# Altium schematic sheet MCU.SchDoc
size A4; Revision: C.2
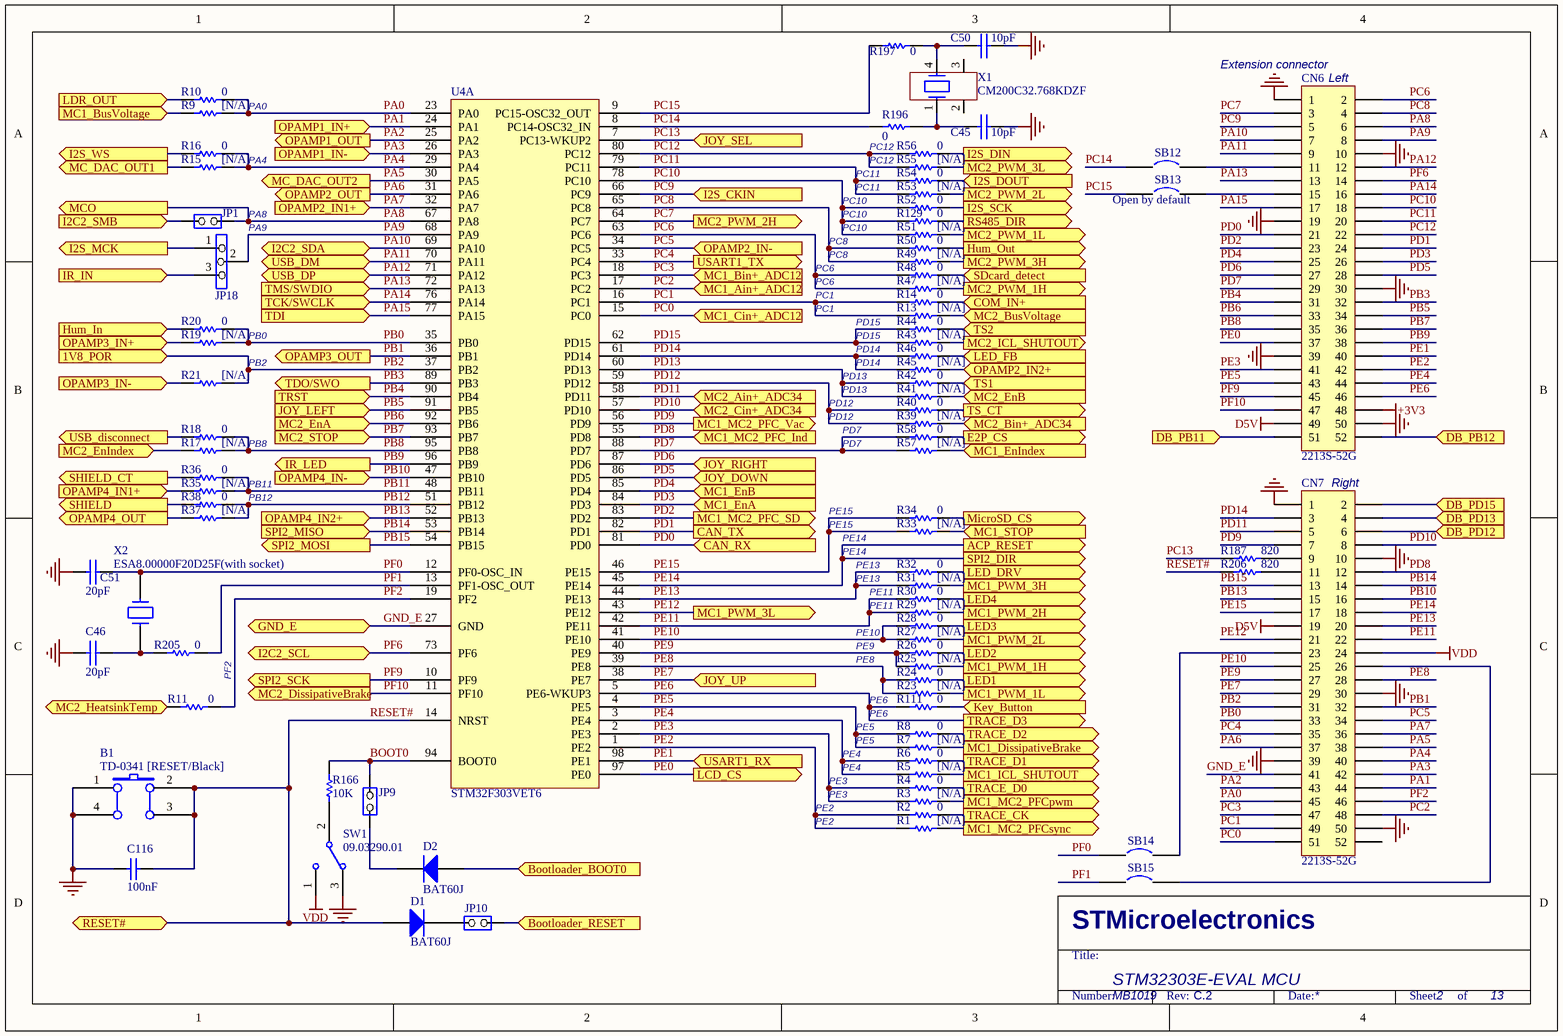
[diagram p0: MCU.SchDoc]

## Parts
B1  TD-0341 [RESET/Black]  [PB10]
C45  10pF  [0603C]
C46  20pF  [0603C]
C50  10pF  [0603C]
C51  20pF  [0603C]
C116  100nF  [0603C]
CN6  2213S-52G  [2*26P]
CN7  2213S-52G  [2*26P]
D1  BAT60J  [SOD-323]
D2  BAT60J  [SOD-323]
JP1  (no value)  [SIP2]
JP9  (no value)  [SIP2]
JP10  (no value)  [SIP2]
JP18  (no value)  [SIP3]
R1  [N/A]  [0603R]
R2  0  [0603R]
R3  [N/A]  [0603R]
R4  0  [0603R]
R5  [N/A]  [0603R]
R6  0  [0603R]
R7  [N/A]  [0603R]
R8  0  [0603R]
R9  [N/A]  [0603R]
R10  0  [0603R]
R11  0  [0603R]
R13  [N/A]  [0603R]
R14  0  [0603R]
R15  [N/A]  [0603R]
R16  0  [0603R]
R17  [N/A]  [0603R]
R18  0  [0603R]
R19  [N/A]  [0603R]
R20  0  [0603R]
R21  [N/A]  [0603R]
R23  [N/A]  [0603R]
R24  0  [0603R]
R25  [N/A]  [0603R]
R26  0  [0603R]
R27  [N/A]  [0603R]
R28  0  [0603R]
R29  [N/A]  [0603R]
R30  0  [0603R]
R31  [N/A]  [0603R]
R32  0  [0603R]
R33  [N/A]  [0603R]
R34  0  [0603R]
R35  [N/A]  [0603R]
R36  0  [0603R]
R37  [N/A]  [0603R]
R38  0  [0603R]
R39  [N/A]  [0603R]
R40  0  [0603R]
R41  [N/A]  [0603R]
R42  0  [0603R]
R43  [N/A]  [0603R]
R44  0  [0603R]
R45  [N/A]  [0603R]
R46  0  [0603R]
R47  [N/A]  [0603R]
R48  0  [0603R]
R49  [N/A]  [0603R]
R50  0  [0603R]
R51  [N/A]  [0603R]
R52  0  [0603R]
R53  [N/A]  [0603R]
R54  0  [0603R]
R55  [N/A]  [0603R]
R56  0  [0603R]
R57  [N/A]  [0603R]
R58  0  [0603R]
R111  0  [0603R]
R129  0  [0603R]
R166  10K  [0603R]
R187  820  [0603R]
R196  0  [0603R]
R197  0  [0603R]
R205  0  [0603R]
R206  820  [0603R]
SB12  (no value)  [JP2_SMD]
SB13  (no value)  [JP2_SMD]
SB14  (no value)  [JP2_SMD]
SB15  (no value)  [JP2_SMD]
SW1  09.03290.01  [SIP3]
U4  STM32F303VET6  [IC149-100-025-B5]  (part A of 2)
X1  CM200C32.768KDZF  [SM8]
X2  ESA8.00000F20D25F(with socket)  [XTAL_socket]

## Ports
1V8_POR (in), ACP_RESET (out), Bootloader_BOOT0 (in), Bootloader_RESET (in), CAN_RX (in), CAN_TX (out), COM_IN+ (in), DB_PB11 (in), DB_PB12 (in), DB_PD12 (in), DB_PD13 (in), DB_PD15 (in), E2P_CS (out), GND_E (bidir), Hum_In (in), Hum_Out (out), I2C2_SCL (bidir), I2C2_SDA (bidir), I2C2_SMB (in), I2S_CKIN (in), I2S_DIN (out), I2S_DOUT (in), I2S_MCK (out), I2S_SCK (out), I2S_WS (out), IR_IN (in), IR_LED (out), JOY_DOWN (in), JOY_LEFT (in), JOY_RIGHT (in), JOY_SEL (in), JOY_UP (in), Key_Button (in), LCD_CS (out), LDR_OUT (in), LED1 (out), LED2 (out), LED3 (out), LED4 (out), LED_DRV (out), LED_FB (in), MC1_Ain+_ADC12 (in), MC1_Bin+_ADC12 (in), MC1_BusVoltage (in), MC1_Cin+_ADC12 (in), MC1_DissipativeBrake (out), MC1_EnA (in), MC1_EnB (in), MC1_EnIndex (in), MC1_ICL_SHUTOUT (out), MC1_MC2_PFC_Ind (in), MC1_MC2_PFC_SD (out), MC1_MC2_PFC_Vac (out), MC1_MC2_PFCpwm (out), MC1_MC2_PFCsync (out), MC1_PWM_1H (out), MC1_PWM_1L (out), MC1_PWM_2H (out), MC1_PWM_2L (out), MC1_PWM_3H (out), MC1_PWM_3L (out), MC1_STOP (in), MC2_Ain+_ADC34 (in), MC2_Bin+_ADC34 (in), MC2_BusVoltage (in), MC2_Cin+_ADC34 (in), MC2_DissipativeBrake (out), MC2_EnA (in), MC2_EnB (in), MC2_EnIndex (in), MC2_HeatsinkTemp (in), MC2_ICL_SHUTOUT (out), MC2_PWM_1H (out), MC2_PWM_1L (out), MC2_PWM_2H (out), MC2_PWM_2L (out), MC2_PWM_3H (out), MC2_PWM_3L (out), MC2_STOP (in), MC_DAC_OUT1 (out), MC_DAC_OUT2 (out), MCO (out), MicroSD_CS (out), OPAMP1_IN+ (in), OPAMP1_IN- (in), OPAMP1_OUT (out), OPAMP2_IN1+ (in), OPAMP2_IN2+ (in), OPAMP2_IN- (in), OPAMP2_OUT (out), OPAMP3_IN+ (in), OPAMP3_IN- (in), OPAMP3_OUT (out), OPAMP4_IN1+ (in), OPAMP4_IN2+ (in), OPAMP4_IN- (in), OPAMP4_OUT (out), RESET# (bidir), RS485_DIR (out), SDcard_detect (in), SHIELD (out), SHIELD_CT (out), SPI2_DIR (out), SPI2_MISO (in), SPI2_MOSI (out), SPI2_SCK (out), TCK/SWCLK (in), TDI (in), TDO/SWO (out), TMS/SWDIO (in), TRACE_CK (out), TRACE_D0 (out), TRACE_D1 (out), TRACE_D2 (out), TRACE_D3 (out), TRST (in), TS1 (in), TS2 (in), TS_CT (out), USART1_RX (in), USART1_TX (out), USB_disconnect (out), USB_DM (bidir), USB_DP (bidir)

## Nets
+3V3: CN6.48
D5V: CN6.49 CN7.19
GND: B1.1(A0) B1.4(A1) C45.2 C46.2 C50.2 C51.2 C116.1 CN6.1 CN6.10 CN6.19 CN6.30 CN6.39 CN6.50 CN7.1 CN7.10 CN7.30 CN7.39 CN7.50 SW1.3
VDD: CN7.24 SW1.1
BOOT0: JP9.2(NO) R166.1 U4.94(BOOT0)
Bootloader_BOOT0: D2.1(A) ; port Bootloader_BOOT0
Bootloader_RESET: JP10.2(NO) ; port Bootloader_RESET
COM_IN+: R14.1 ; port COM_IN+
DB_PB11: CN6.51 ; port DB_PB11
DB_PB12: CN6.52 ; port DB_PB12
DB_PD12: CN7.6 ; port DB_PD12
DB_PD13: CN7.4 ; port DB_PD13
DB_PD15: CN7.2 ; port DB_PD15
E2P_CS: R58.1 ; port E2P_CS
GND_E: CN7.41 U4.27(GND) ; port GND_E
Hum_In: R20.2 ; port Hum_In
Hum_Out: R50.1 ; port Hum_Out
I2C2_SMB: JP1.2(NO) ; port I2C2_SMB
I2S_DIN: R56.1 ; port I2S_DIN
I2S_DOUT: R54.1 ; port I2S_DOUT
I2S_MCK: JP18.1 ; port I2S_MCK
I2S_SCK: R52.1 ; port I2S_SCK
I2S_WS: R16.2 ; port I2S_WS
IR_IN: JP18.3 ; port IR_IN
Key_Button: R111.1 ; port Key_Button
LDR_OUT: R10.2 ; port LDR_OUT
LED1: R24.1 ; port LED1
LED2: R26.1 ; port LED2
LED3: R28.1 ; port LED3
LED4: R30.1 ; port LED4
LED_DRV: R32.1 ; port LED_DRV
LED_FB: R46.1 ; port LED_FB
MC1_BusVoltage: R9.2 ; port MC1_BusVoltage
MC1_DissipativeBrake: R7.1 ; port MC1_DissipativeBrake
MC1_EnIndex: R57.1 ; port MC1_EnIndex
MC1_ICL_SHUTOUT: R5.1 ; port MC1_ICL_SHUTOUT
MC1_MC2_PFCpwm: R3.1 ; port MC1_MC2_PFCpwm
MC1_MC2_PFCsync: R1.1 ; port MC1_MC2_PFCsync
MC1_PWM_1H: R25.1 ; port MC1_PWM_1H
MC1_PWM_1L: R23.1 ; port MC1_PWM_1L
MC1_PWM_2H: R29.1 ; port MC1_PWM_2H
MC1_PWM_2L: R27.1 ; port MC1_PWM_2L
MC1_PWM_3H: R31.1 ; port MC1_PWM_3H
MC1_STOP: R33.1 ; port MC1_STOP
MC2_Bin+_ADC34: R39.1 ; port MC2_Bin+_ADC34
MC2_BusVoltage: R13.1 ; port MC2_BusVoltage
MC2_EnB: R41.1 ; port MC2_EnB
MC2_EnIndex: R17.2 ; port MC2_EnIndex
MC2_HeatsinkTemp: R11.2 ; port MC2_HeatsinkTemp
MC2_ICL_SHUTOUT: R43.1 ; port MC2_ICL_SHUTOUT
MC2_PWM_1H: R47.1 ; port MC2_PWM_1H
MC2_PWM_1L: R51.1 ; port MC2_PWM_1L
MC2_PWM_2L: R53.1 ; port MC2_PWM_2L
MC2_PWM_3H: R49.1 ; port MC2_PWM_3H
MC2_PWM_3L: R55.1 ; port MC2_PWM_3L
MC_DAC_OUT1: R15.2 ; port MC_DAC_OUT1
MicroSD_CS: R34.1 ; port MicroSD_CS
OPAMP2_IN2+: R45.1 ; port OPAMP2_IN2+
OPAMP3_IN+: R19.2 ; port OPAMP3_IN+
OPAMP3_IN-: R21.2 ; port OPAMP3_IN-
OPAMP4_IN1+: R35.2 ; port OPAMP4_IN1+
OPAMP4_OUT: R37.2 ; port OPAMP4_OUT
PA0: CN7.45 R9.1 R10.1 U4.23(PA0)
PA1: CN7.44 U4.24(PA1) ; port OPAMP1_IN+
PA2: CN7.43 U4.25(PA2) ; port OPAMP1_OUT
PA3: CN7.42 U4.26(PA3) ; port OPAMP1_IN-
PA4: CN7.40 R15.1 R16.1 U4.29(PA4)
PA5: CN7.38 U4.30(PA5) ; port MC_DAC_OUT2
PA6: CN7.37 U4.31(PA6) ; port OPAMP2_OUT
PA7: CN7.36 U4.32(PA7) ; port OPAMP2_IN1+
PA8: CN6.6 JP1.1(COMMON) U4.67(PA8) ; port MCO
PA9: CN6.8 JP18.2 U4.68(PA9)
PA10: CN6.7 U4.69(PA10) ; port I2C2_SDA
PA11: CN6.9 U4.70(PA11) ; port USB_DM
PA12: CN6.12 U4.71(PA12) ; port USB_DP
PA13: CN6.13 U4.72(PA13) ; port TMS/SWDIO
PA14: CN6.16 U4.76(PA14) ; port TCK/SWCLK
PA15: CN6.17 U4.77(PA15) ; port TDI
PB0: CN7.33 R19.1 R20.1 U4.35(PB0)
PB1: CN7.32 U4.36(PB1) ; port OPAMP3_OUT
PB2: CN7.31 R21.1 U4.37(PB2) ; port 1V8_POR
PB3: CN6.32 U4.89(PB3) ; port TDO/SWO
PB4: CN6.31 U4.90(PB4) ; port TRST
PB5: CN6.34 U4.91(PB5) ; port JOY_LEFT
PB6: CN6.33 U4.92(PB6) ; port MC2_EnA
PB7: CN6.36 U4.93(PB7) ; port MC2_STOP
PB8: CN6.35 R17.1 R18.1 U4.95(PB8)
PB9: CN6.38 U4.96(PB9) ; port IR_LED
PB10: CN7.16 U4.47(PB10) ; port OPAMP4_IN-
PB11: R35.1 R36.1 U4.48(PB11)
PB12: R37.1 R38.1 U4.51(PB12)
PB13: CN7.15 U4.52(PB13) ; port OPAMP4_IN2+
PB14: CN7.14 U4.53(PB14) ; port SPI2_MISO
PB15: CN7.13 U4.54(PB15) ; port SPI2_MOSI
PC0: CN7.51 U4.15(PC0) ; port MC1_Cin+_ADC12
PC1: CN7.49 R13.2 R14.2 U4.16(PC1)
PC2: CN7.48 U4.17(PC2) ; port MC1_Ain+_ADC12
PC3: CN7.47 U4.18(PC3) ; port MC1_Bin+_ADC12
PC4: CN7.35 U4.33(PC4) ; port USART1_TX
PC5: CN7.34 U4.34(PC5) ; port OPAMP2_IN-
PC6: CN6.2 R47.2 R48.2 U4.63(PC6)
PC7: CN6.3 U4.64(PC7) ; port MC2_PWM_2H
PC8: CN6.4 R49.2 R50.2 U4.65(PC8)
PC9: CN6.5 U4.66(PC9) ; port I2S_CKIN
PC10: CN6.18 R51.2 R52.2 R129.2 U4.78(PC10)
PC11: CN6.20 R53.2 R54.2 U4.79(PC11)
PC12: CN6.22 R55.2 R56.2 U4.80(PC12)
PC13: R187.1 U4.7(PC13-WKUP2) ; port JOY_SEL
PC14: R196.2 SB12.1 U4.8(PC14-OSC32_IN)
PC15: R197.2 SB13.1 U4.9(PC15-OSC32_OUT)
PD0: CN6.21 U4.81(PD0) ; port CAN_RX
PD1: CN6.24 U4.82(PD1) ; port CAN_TX
PD2: CN6.23 U4.83(PD2) ; port MC1_MC2_PFC_SD
PD3: CN6.26 U4.84(PD3) ; port MC1_EnA
PD4: CN6.25 U4.85(PD4) ; port MC1_EnB
PD5: CN6.28 U4.86(PD5) ; port JOY_DOWN
PD6: CN6.27 U4.87(PD6) ; port JOY_RIGHT
PD7: CN6.29 R57.2 R58.2 U4.88(PD7)
PD8: CN7.12 U4.55(PD8) ; port MC1_MC2_PFC_Ind
PD9: CN7.7 U4.56(PD9) ; port MC1_MC2_PFC_Vac
PD10: CN7.8 U4.57(PD10) ; port MC2_Cin+_ADC34
PD11: CN7.5 U4.58(PD11) ; port MC2_Ain+_ADC34
PD12: R39.2 R40.2 U4.59(PD12)
PD13: R41.2 R42.2 U4.60(PD13)
PD14: CN7.3 R45.2 R46.2 U4.61(PD14)
PD15: R43.2 R44.2 U4.62(PD15)
PE0: CN6.37 U4.97(PE0) ; port LCD_CS
PE1: CN6.40 U4.98(PE1) ; port USART1_RX
PE2: CN6.42 R1.2 R2.2 U4.1(PE2)
PE3: CN6.41 R3.2 R4.2 U4.2(PE3)
PE4: CN6.44 R5.2 R6.2 U4.3(PE4)
PE5: CN6.43 R7.2 R8.2 U4.4(PE5)
PE6: CN6.46 R111.2 U4.5(PE6-WKUP3) ; port TRACE_D3
PE7: CN7.29 U4.38(PE7) ; port JOY_UP
PE8: CN7.28 R23.2 R24.2 U4.39(PE8)
PE9: CN7.27 R25.2 R26.2 U4.40(PE9)
PE10: CN7.25 R27.2 R28.2 U4.41(PE10)
PE11: CN7.22 R29.2 R30.2 U4.42(PE11)
PE12: CN7.21 U4.43(PE12) ; port MC1_PWM_3L
PE13: CN7.20 R31.2 R32.2 U4.44(PE13)
PE14: CN7.18 U4.45(PE14) ; port ACP_RESET, port SPI2_DIR
PE15: CN7.17 R33.2 R34.2 U4.46(PE15)
PF0: C51.1 SB14.1 U4.12(PF0-OSC_IN) X2.2
PF1: R205.1 SB15.1 U4.13(PF1-OSC_OUT)
PF2: CN7.46 R11.1 U4.19(PF2)
PF6: CN6.14 U4.73(PF6) ; port I2C2_SCL
PF9: CN6.45 U4.10(PF9) ; port SPI2_SCK
PF10: CN6.47 U4.11(PF10) ; port MC2_DissipativeBrake
RESET#: B1.2(B0) B1.3(B1) C116.2 D1.1(A) R206.2 U4.14(NRST) ; port RESET#
RS485_DIR: R129.1 ; port RS485_DIR
SDcard_detect: R48.1 ; port SDcard_detect
SHIELD: R38.2 ; port SHIELD
SHIELD_CT: R36.2 ; port SHIELD_CT
TRACE_CK: R2.1 ; port TRACE_CK
TRACE_D0: R4.1 ; port TRACE_D0
TRACE_D1: R6.1 ; port TRACE_D1
TRACE_D2: R8.1 ; port TRACE_D2
TS1: R42.1 ; port TS1
TS2: R44.1 ; port TS2
TS_CT: R40.1 ; port TS_CT
USB_disconnect: R18.2 ; port USB_disconnect
NetC45_1: C45.1 R196.1 X1.1
NetC46_1: C46.1 R205.2 X2.1
NetC50_1: C50.1 R197.1 X1.4
NetCN6_11: CN6.11 SB12.2
NetCN6_15: CN6.15 SB13.2
NetCN7_9: CN7.9 R187.2
NetCN7_11: CN7.11 R206.1
NetCN7_23: CN7.23 SB14.2
NetCN7_26: CN7.26 SB15.2
NetD1_2: D1.2(K) JP10.1(COMMON)
NetD2_2: D2.2(K) JP9.1(COMMON)
NetR166_2: R166.2 SW1.2

Not connected (* = marked no-connect by the designer): CN7 52; X1 2 3

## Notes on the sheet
- PA0
- (near CN6) Extension connector
- (near CN6) Left
- PA4
- PC11
- PC12
- PA8
- PA9
- PC8
- PC10
- (near SB13) Open by default
- PC1
- PC6
- PB0
- PB2
- PD13
- PD14
- PD15
- PB8
- PD12
- PD7
- PB11
- PB12
- PE15
- (near CN7) Right
- PE14
- PE13
- PE9
- PE10
- PE11
- PF2
- PE8
- PE6
- PE3
- PE4
- PE5
- PE2
- STM32303E-EVAL MCU
- MB1019
- 2
- 13

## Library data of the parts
B1 = SW PUSHBUTTON: SE PUSHBUTTON
C45 C46 C50 C51 = CAP: Capacitor
C116 = CAP: Capacitor; Value: 100pF
CN6 CN7 = Header 26X2_1: Header, 26-Pin, Dual row
D1 D2 = Diode: Default Diode; Code - JEDEC: DO-214-AB
JP1 JP9 JP10 = JP2
JP18 = Jumper3
R1-R11 R13-R21 R23-R58 R111 R129 R187 R196 R197 R205 R206 = Res1: Resistor; Value: 1K
R166 = res1: Resistor; Value: 1K
SB12-SB15 = Circuit Breaker
SW1 = SW-SPDT: SPDT Subminiature Toggle Switch, Right Angle Mounting, Vertical Actuation; Revision 1: Jul-2002: Re-released for DXP Platform.; Revision 2: 17-Dec-2003: Schematic revised, PCB Footprint replaced.
U4 = STM32F303VCT6
X1 = MC306
X2 = CRYSTAL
